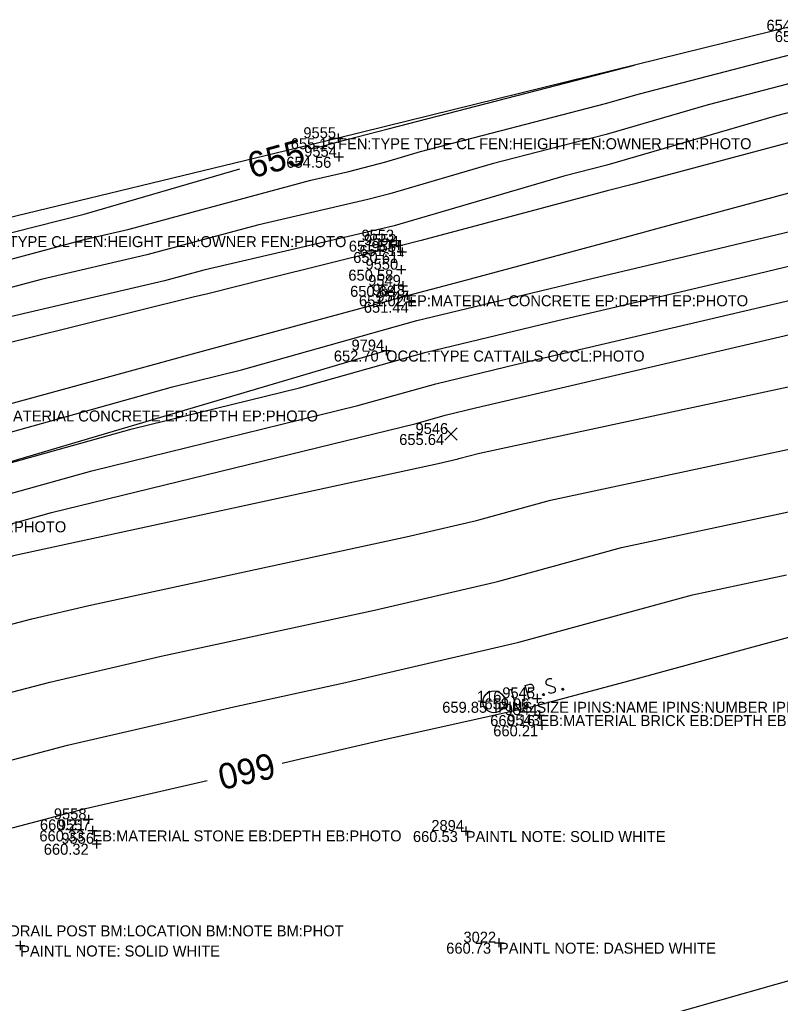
# Model space of a CAD drawing. Extents: x 2129350 to 2137777, y 657588 to 659885.
# Drawn here: x 2134268.7 to 2134351.9, y 659078.5 to 659186 of the extents above; entities that cross this region are included whole.
import ezdxf

# ---------------------------------------------------------------- set-up
doc = ezdxf.new("R2010")
doc.units = 0
for name, color, linetype in [('DT_X_Contour_Major', 7, 'Continuous'), ('DT_X_Contour_Minor', 7, 'Continuous'), ('DT_X_TIN_Hull', 7, 'Continuous'), ('PV_X_COP', 7, 'Continuous'), ('SV_P_Mon_Cells_Set', 7, 'Continuous'), ('SV_X_Occupation_Line', 7, 'Continuous'), ('SV_X_Random_Point', 7, 'Continuous'), ('SV_X_Shot_Marker', 7, 'Continuous'), ('SV_X_Text_Comment', 7, 'Continuous'), ('SV_X_Text_Elevation', 7, 'Continuous'), ('SV_X_Text_Name', 7, 'Continuous')]:
    doc.layers.add(name, color=color, linetype=linetype)

msp = doc.modelspace()

# ---------------------------------------------------------------- linework, layer by layer
at = {"layer": 'DT_X_Contour_Major'}
for points in [[(2134300.87, 659171.9), (2134303.53, 659172.62), (2134304.47, 659172.86), (2134309.01, 659174.04), (2134335.93, 659181)], [(2134195.69, 659145.79), (2134216.4, 659150.64), (2134219.64, 659151.42), (2134235.81, 659155.2), (2134255.8, 659159.88), (2134260.05, 659160.76), (2134275.77, 659164.7), (2134292.78, 659169.65)], [(2134259.01, 659128.73), (2134262.9, 659129.67), (2134267.26, 659130.72), (2134272.2, 659132.1), (2134312.05, 659141.85), (2134315.24, 659142.75), (2134318.55, 659143.54), (2134356.18, 659152.33)], [(2134297.41, 659104.74), (2134300.03, 659105.35), (2134300.54, 659105.46), (2134308.9, 659107.4), (2134317.93, 659109.37), (2134324.93, 659110.95), (2134325.38, 659111.05), (2134335.3, 659113.73), (2134348.51, 659117.34), (2134360.34, 659120.53), (2134371.28, 659123.52), (2134393.63, 659129.35), (2134394.27, 659129.51)], [(2134192.04, 659079.6), (2134201.65, 659081.72), (2134201.85, 659081.78), (2134201.93, 659081.92), (2134203.56, 659082.44), (2134216.42, 659084.98), (2134222.44, 659086.3), (2134228.12, 659087.64), (2134230.5, 659088.18), (2134236.1, 659089.42), (2134246.48, 659092.02), (2134254.29, 659094.11), (2134254.9, 659094.24), (2134275.91, 659099.77), (2134289.22, 659102.85)]]:
    msp.add_lwpolyline(points, dxfattribs=at)
at = {"layer": 'DT_X_Contour_Minor'}
for points in [[(2134152.76, 659131.84), (2134168.03, 659135.54), (2134168.24, 659135.6), (2134176.5, 659137.84), (2134192.24, 659141.51), (2134200.65, 659143.79), (2134216.49, 659147.5), (2134224.81, 659149.5), (2134236.7, 659152.28), (2134254.85, 659156.52), (2134260.96, 659157.99), (2134275.77, 659161.94), (2134280.7, 659163.09), (2134300.56, 659168.43), (2134304.69, 659169.39), (2134308.74, 659170.44), (2134312.54, 659171.55), (2134332.75, 659176.79), (2134336.49, 659177.87), (2134356.95, 659183.17)], [(2134357, 659180.03), (2134343.97, 659176.66), (2134332.83, 659173.43), (2134320.38, 659170.2), (2134309.2, 659166.94), (2134306.79, 659166.32), (2134294.71, 659163.52), (2134282.62, 659160.26), (2134271.08, 659157.58), (2134261.88, 659155.12), (2134249.21, 659152.07), (2134237.6, 659149.36), (2134229.99, 659147.58), (2134216.57, 659144.35), (2134206.19, 659141.92), (2134192.34, 659138.17), (2134182.17, 659135.8), (2134168.28, 659132.03), (2134167.92, 659131.93), (2134158.21, 659129.58)], [(2134357.06, 659176.9), (2134351.46, 659175.45), (2134332.91, 659170.07), (2134328.21, 659168.85), (2134309.66, 659163.45), (2134308.89, 659163.25), (2134288.86, 659158.6), (2134284.53, 659157.44), (2134266.4, 659153.21), (2134262.8, 659152.25), (2134243.57, 659147.62), (2134238.49, 659146.44), (2134235.17, 659145.66), (2134216.66, 659141.21), (2134211.73, 659140.06), (2134192.45, 659134.84), (2134187.85, 659133.76), (2134168.32, 659128.46), (2134167.81, 659128.32), (2134163.65, 659127.32), (2134143.51, 659122.48)], [(2134354.27, 659172.9), (2134335.82, 659167.99), (2134332.96, 659167.27), (2134312.59, 659161.84), (2134310.18, 659161.23), (2134308.22, 659160.74), (2134295.76, 659157.65), (2134289.27, 659156.02), (2134287.68, 659155.64), (2134269.19, 659151.04), (2134263.57, 659149.7), (2134247.74, 659145.92), (2134240.17, 659144.03), (2134226.21, 659140.7), (2134216.67, 659138.28), (2134216.49, 659138.23), (2134204.56, 659135.1), (2134192.21, 659131.83), (2134182.68, 659129.32), (2134167.97, 659125.44), (2134167.73, 659125.38), (2134163.65, 659124.36), (2134152.8, 659121.69)], [(2134149.54, 659114.15), (2134168.53, 659118.99), (2134169.51, 659119.25), (2134176.36, 659121.06), (2134193.45, 659125.56), (2134215.07, 659131.32), (2134217.44, 659131.95), (2134217.78, 659132.04), (2134219.45, 659132.44), (2134241.19, 659137.52), (2134253.61, 659140.56), (2134264.15, 659143.06), (2134281.64, 659147.81), (2134287.19, 659149.33), (2134309.81, 659155.46), (2134311.1, 659155.81), (2134317.07, 659157.39), (2134335.2, 659162.28), (2134338.65, 659163.23), (2134359.31, 659168.81)], [(2134143.24, 659109.7), (2134164.52, 659115.16), (2134169.55, 659116.45), (2134190.08, 659121.55), (2134209.48, 659126.37), (2134227.5, 659131.1), (2134227.81, 659131.17), (2134246.92, 659135.78), (2134264.95, 659140.12), (2134285.42, 659145.84), (2134292.96, 659147.69), (2134312.13, 659153.08), (2134332.05, 659157.88), (2134341.43, 659160.07), (2134360.86, 659164.73)], [(2134149.49, 659107.65), (2134166.17, 659111.93), (2134170.12, 659112.94), (2134186.21, 659116.94), (2134201.41, 659120.72), (2134237.74, 659130.24), (2134237.97, 659130.3), (2134252.24, 659133.74), (2134265.72, 659136.99), (2134281.01, 659141.26), (2134299.32, 659145.74), (2134313.17, 659149.64), (2134327.55, 659153.1), (2134348.69, 659158.03), (2134362.22, 659161.28)], [(2134155.75, 659105.6), (2134167.83, 659108.7), (2134170.68, 659109.44), (2134182.33, 659112.33), (2134193.34, 659115.07), (2134247.98, 659129.39), (2134248.13, 659129.43), (2134257.57, 659131.71), (2134266.49, 659133.85), (2134276.6, 659136.68), (2134305.69, 659143.8), (2134314.2, 659146.19), (2134323.05, 659148.32), (2134355.95, 659156)], [(2134127.59, 659090.34), (2134168.25, 659101.51), (2134171.13, 659102.25), (2134171.81, 659102.42), (2134174.59, 659103.11), (2134177.21, 659103.77), (2134261.53, 659125.87), (2134265.68, 659126.88), (2134267.84, 659127.35), (2134268.08, 659127.41), (2134268.35, 659127.48), (2134314.46, 659137.47), (2134316.66, 659137.98), (2134316.74, 659138), (2134318.98, 659138.61), (2134362.91, 659148.03)], [(2134154.98, 659094.1), (2134169.97, 659096.91), (2134172.67, 659097.63), (2134174.56, 659097.76), (2134174.91, 659097.83), (2134220.76, 659109.32), (2134222.58, 659109.9), (2134223.89, 659110.16), (2134224.07, 659110.19), (2134225.39, 659110.54), (2134264.61, 659119.07), (2134270.04, 659120.5), (2134276.27, 659121.94), (2134310.98, 659129.47), (2134318.67, 659131.25), (2134318.92, 659131.31), (2134326.75, 659133.45), (2134359.46, 659140.46)], [(2134127.31, 659081.14), (2134164.1, 659088.04), (2134174.01, 659090.7), (2134180.94, 659091.15), (2134182.24, 659091.4), (2134204.15, 659096.9), (2134216.24, 659100.74), (2134225.04, 659102.48), (2134226.23, 659102.72), (2134235.02, 659105.07), (2134261.37, 659110.8), (2134272, 659113.59), (2134284.19, 659116.41), (2134307.5, 659121.46), (2134320.67, 659124.52), (2134321.1, 659124.62), (2134334.51, 659128.28), (2134356.01, 659132.89)], [(2134158.23, 659079.17), (2134175.35, 659083.76), (2134186.81, 659084.51), (2134186.86, 659084.53), (2134187.34, 659084.2), (2134188.45, 659084.18), (2134189.48, 659084.43), (2134189.96, 659085.24), (2134209.9, 659091.59), (2134226.18, 659094.81), (2134228.38, 659095.24), (2134244.66, 659099.59), (2134258.14, 659102.52), (2134273.96, 659106.68), (2134292.11, 659110.88), (2134304.02, 659113.46), (2134322.68, 659117.79), (2134323.28, 659117.93), (2134342.28, 659123.12), (2134352.56, 659125.32)]]:
    msp.add_lwpolyline(points, dxfattribs=at)
at = {"layer": 'DT_X_TIN_Hull'}
msp.add_lwpolyline([(2134356.03, 659185.95), (2134303.52, 659173.01), (2134259.23, 659162.31), (2134216.07, 659153.31), (2134168.25, 659141.96), (2134125.88, 659132.55), (2134109.05, 659128.86), (2134056.89, 659117.03), (2133999.59, 659103.37), (2133973.21, 659091.25), (2133972.95, 659091.39), (2133971.1, 659091.46), (2133969.76, 659091.14), (2133967.6, 659091.08), (2133965.7, 659091.19), (2133965.45, 659091.23), (2133933.98, 659084.79), (2133923.28, 659083.03), (2133873.95, 659069.27), (2133819.31, 659054.81), (2133767.48, 659040.46), (2133725.98, 659030.57)], dxfattribs=at)
at = {"layer": 'PV_X_COP'}
msp.add_lwpolyline([(2134372.8, 659086.61), (2134323.79, 659072.7), (2134275.99, 659059.69), (2134222.68, 659044.63), (2134179.75, 659033.13), (2134131.31, 659020.04), (2134083.27, 659006.66), (2134034.91, 658993.22), (2133987.27, 658980.27), (2133938.9, 658966.72), (2133890.03, 658953.66), (2133841.98, 658940.1), (2133794.81, 658927.21), (2133746.12, 658913.94)], dxfattribs=at)
at = {"layer": 'SV_P_Mon_Cells_Set'}
for points in [[(2134324.41, 659111.67), (2134323.98, 659113.21), (2134324.49, 659113.35), (2134324.55, 659113.35), (2134324.63, 659113.35), (2134324.67, 659113.33), (2134324.7, 659113.32), (2134324.76, 659113.27), (2134324.81, 659113.22), (2134324.86, 659113.13), (2134324.9, 659112.98), (2134324.9, 659112.93), (2134324.9, 659112.85), (2134324.88, 659112.75), (2134324.85, 659112.71), (2134324.83, 659112.67), (2134324.78, 659112.63), (2134324.7, 659112.6), (2134324.19, 659112.46)], [(2134326.91, 659113.9), (2134326.88, 659113.92), (2134326.84, 659113.94), (2134326.74, 659113.95), (2134326.61, 659113.94), (2134326.53, 659113.92), (2134326.5, 659113.91), (2134326.37, 659113.83), (2134326.27, 659113.73), (2134326.22, 659113.61), (2134326.23, 659113.51), (2134326.25, 659113.43), (2134326.3, 659113.34), (2134326.41, 659113.28), (2134327.09, 659113.08), (2134327.16, 659113.05), (2134327.19, 659113), (2134327.23, 659112.94), (2134327.25, 659112.86), (2134327.26, 659112.79), (2134327.27, 659112.74), (2134327.26, 659112.67), (2134327.26, 659112.61), (2134327.24, 659112.57), (2134327.22, 659112.53), (2134327.2, 659112.49), (2134327.16, 659112.46), (2134327.13, 659112.44), (2134327.04, 659112.4), (2134326.89, 659112.36), (2134326.79, 659112.35), (2134326.63, 659112.4), (2134326.52, 659112.45)], [(2134328.04, 659112.9), (2134328.09, 659112.91), (2134328.13, 659112.9), (2134328.17, 659112.86), (2134328.19, 659112.79), (2134328.17, 659112.74), (2134328.15, 659112.7), (2134328.09, 659112.69), (2134328.05, 659112.71), (2134328.01, 659112.74), (2134327.99, 659112.81), (2134328.01, 659112.86), (2134328.04, 659112.9)], [(2134322.3, 659112.74), (2134322.64, 659112.84)], [(2134322.9, 659111.25), (2134322.47, 659112.79)], [(2134325.93, 659112.31), (2134325.98, 659112.33), (2134326.02, 659112.31), (2134326.07, 659112.27), (2134326.09, 659112.21), (2134326.07, 659112.15), (2134326.04, 659112.12), (2134325.99, 659112.11), (2134325.95, 659112.12), (2134325.91, 659112.16), (2134325.89, 659112.22), (2134325.91, 659112.28), (2134325.93, 659112.31)], [(2134322.73, 659111.2), (2134323.07, 659111.3)], [(2134323.76, 659111.71), (2134323.82, 659111.73), (2134323.86, 659111.71), (2134323.9, 659111.67), (2134323.92, 659111.61), (2134323.9, 659111.55), (2134323.88, 659111.52), (2134323.82, 659111.51), (2134323.78, 659111.52), (2134323.74, 659111.56), (2134323.72, 659111.62), (2134323.74, 659111.68), (2134323.76, 659111.71)]]:
    msp.add_lwpolyline(points, dxfattribs=at)
msp.add_circle((2134320.57, 659111.43), 1.2, dxfattribs=at)
at = {"layer": 'SV_X_Occupation_Line'}
msp.add_lwpolyline([(2133964.23, 659050.82), (2133988.96, 659052.85), (2134023.9, 659066.14), (2134068.85, 659084.35), (2134158.11, 659108.79), (2134245.54, 659131.15), (2134308.77, 659149.81)], dxfattribs=at)
at = {"layer": 'SV_X_Random_Point'}
for p, q in [((2134315.19, 659140.02), (2134316.53, 659141.36)), ((2134315.19, 659141.36), (2134316.53, 659140.02))]:
    msp.add_line(p, q, dxfattribs=at)
at = {"layer": 'SV_X_Shot_Marker'}
for p, q in [((2134303.52, 659173.51), (2134303.52, 659172.51)), ((2134303.02, 659173.01), (2134304.02, 659173.01)), ((2134303.52, 659173.01), (2134303.52, 659173.01)), ((2134303.1, 659170.98), (2134304.1, 659170.98)), ((2134303.6, 659171.48), (2134303.6, 659170.48)), ((2134303.6, 659170.98), (2134303.6, 659170.98)), ((2134309.37, 659161.82), (2134310.37, 659161.82)), ((2134309.62, 659161.33), (2134310.62, 659161.33)), ((2134309.87, 659162.32), (2134309.87, 659161.32)), ((2134309.87, 659161.82), (2134309.87, 659161.82)), ((2134310.12, 659161.83), (2134310.12, 659160.83)), ((2134310.12, 659161.33), (2134310.12, 659161.33)), ((2134310.02, 659160.58), (2134311.02, 659160.58)), ((2134310.52, 659161.08), (2134310.52, 659160.08)), ((2134310.52, 659160.58), (2134310.52, 659160.58)), ((2134310.42, 659159.15), (2134310.42, 659158.15)), ((2134309.92, 659158.65), (2134310.92, 659158.65)), ((2134310.42, 659158.65), (2134310.42, 659158.65)), ((2134310.62, 659157.38), (2134310.62, 659156.38)), ((2134310.12, 659156.88), (2134311.12, 659156.88)), ((2134310.62, 659156.88), (2134310.62, 659156.88)), ((2134311.08, 659156.34), (2134311.08, 659155.34)), ((2134310.58, 659155.84), (2134311.58, 659155.84)), ((2134311.01, 659155.14), (2134312.01, 659155.14)), ((2134311.08, 659155.84), (2134311.08, 659155.84)), ((2134311.51, 659155.64), (2134311.51, 659154.64)), ((2134311.51, 659155.14), (2134311.51, 659155.14)), ((2134308.27, 659149.81), (2134309.27, 659149.81)), ((2134308.77, 659150.31), (2134308.77, 659149.31)), ((2134308.77, 659149.81), (2134308.77, 659149.81)), ((2134324.78, 659111.81), (2134325.78, 659111.81)), ((2134325.28, 659112.31), (2134325.28, 659111.31)), ((2134325.28, 659111.81), (2134325.28, 659111.81)), ((2134325.04, 659109.98), (2134326.04, 659109.98)), ((2134325.54, 659110.48), (2134325.54, 659109.48)), ((2134325.54, 659109.98), (2134325.54, 659109.98)), ((2134325.31, 659108.86), (2134326.31, 659108.86)), ((2134325.81, 659109.36), (2134325.81, 659108.36)), ((2134325.81, 659108.86), (2134325.81, 659108.86)), ((2134276.25, 659099.09), (2134276.25, 659098.09)), ((2134275.75, 659098.59), (2134276.75, 659098.59)), ((2134276.25, 659098.59), (2134276.25, 659098.59)), ((2134276.67, 659097.88), (2134276.67, 659096.88)), ((2134276.17, 659097.38), (2134277.17, 659097.38)), ((2134276.67, 659097.38), (2134276.67, 659097.38)), ((2134316.98, 659097.31), (2134317.98, 659097.31)), ((2134317.48, 659097.81), (2134317.48, 659096.81)), ((2134317.48, 659097.31), (2134317.48, 659097.31)), ((2134276.63, 659095.92), (2134277.63, 659095.92)), ((2134277.13, 659096.42), (2134277.13, 659095.42)), ((2134277.13, 659095.92), (2134277.13, 659095.92)), ((2134268.77, 659085.3), (2134268.77, 659084.3)), ((2134320.61, 659085.11), (2134321.61, 659085.11)), ((2134321.11, 659085.61), (2134321.11, 659084.61)), ((2134321.11, 659085.11), (2134321.11, 659085.11)), ((2134268.27, 659084.8), (2134269.27, 659084.8)), ((2134268.77, 659084.8), (2134268.77, 659084.8))]:
    msp.add_line(p, q, dxfattribs=at)

# ---------------------------------------------------------------- texts
at = {"layer": 'DT_X_Contour_Major'}
for s, rotation, p in [('655', 15.5327, (2134294.1, 659168.6)), ('660', 193.0186, (2134296.26, 659105.91))]:
    msp.add_text(s, height=2.8, rotation=rotation, dxfattribs=at).set_placement(p)
at = {"layer": 'SV_X_Text_Comment'}
for s, p in [('FEN:TYPE TYPE CL FEN:HEIGHT FEN:OWNER FEN:PHOTO', (2134303.52, 659171.81)), ('FEN:TYPE TYPE CL FEN:HEIGHT FEN:OWNER FEN:PHOTO', (2134259.23, 659161.11)), ('EP:MATERIAL CONCRETE EP:DEPTH EP:PHOTO', (2134311.08, 659154.65)), ('OCCL:TYPE CATTAILS OCCL:PHOTO', (2134308.77, 659148.61)), ('EP:MATERIAL CONCRETE EP:DEPTH EP:PHOTO', (2134264.06, 659142.06)), ('OCCL:TYPE CATTAILS OCCL:PHOTO', (2134245.54, 659129.95)), ('IPINS:SIZE IPINS:NAME IPINS:NUMBER IPINS:NOTE IPINS:PHOTO', (2134320.57, 659110.23)), ('EB:MATERIAL BRICK EB:DEPTH EB:PHOTO', (2134325.54, 659108.78)), ('EB:MATERIAL STONE EB:DEPTH EB:PHOTO', (2134276.67, 659096.18)), ('PAINTL NOTE: SOLID WHITE', (2134317.48, 659096.11)), ('BM:DESCRIPTION BENCH TIE EASTERN GUARDRAIL POST BM:LOCATION BM:NOTE BM:PHOT', (2134231.64, 659085.8)), ('PAINTL NOTE: DASHED WHITE', (2134321.11, 659083.91)), ('PAINTL NOTE: SOLID WHITE', (2134268.77, 659083.6))]:
    msp.add_text(s, height=1.2, dxfattribs=at).set_placement(p)
at = {"layer": 'SV_X_Text_Elevation'}
for s, p in [('654.97', (2134350.36, 659184.75)), ('654.53', (2134351.27, 659183.52)), ('655.15', (2134298.35, 659171.81)), ('654.56', (2134297.87, 659169.78)), ('651.57', (2134304.7, 659160.62)), ('651.11', (2134305.86, 659160.13)), ('650.61', (2134305.18, 659159.38)), ('650.58', (2134304.65, 659157.45)), ('650.68', (2134304.84, 659155.68)), ('651.02', (2134305.81, 659154.65)), ('651.44', (2134306.34, 659153.94)), ('652.70', (2134303.06, 659148.61)), ('655.64', (2134310.21, 659139.49)), ('659.96', (2134319.53, 659110.61)), ('659.85', (2134314.91, 659110.23)), ('660.16', (2134320.16, 659108.78)), ('660.21', (2134320.49, 659107.66)), ('660.21', (2134270.93, 659097.39)), ('660.33', (2134270.87, 659096.18)), ('660.53', (2134311.71, 659096.11)), ('660.32', (2134271.35, 659094.72)), ('660.73', (2134315.35, 659083.91))]:
    msp.add_text(s, height=1.2, dxfattribs=at).set_placement(p)
at = {"layer": 'SV_X_Text_Name'}
for s, p in [('9555', (2134299.73, 659173.01)), ('9554', (2134299.82, 659170.98)), ('9553', (2134306.08, 659161.82)), ('9552', (2134306.35, 659161.33)), ('9551', (2134307.17, 659160.58)), ('9550', (2134306.52, 659158.65)), ('9549', (2134306.81, 659156.88)), ('9548', (2134307.28, 659155.84)), ('9547', (2134307.71, 659155.14)), ('9794', (2134304.99, 659149.81)), ('9546', (2134311.99, 659140.69)), ('9545', (2134321.48, 659111.81)), ('116', (2134318.71, 659111.43)), ('9544', (2134321.75, 659109.98)), ('9543', (2134322.02, 659108.86)), ('9558', (2134272.45, 659098.59)), ('9557', (2134272.88, 659097.38)), ('2894', (2134313.72, 659097.31)), ('9556', (2134273.27, 659095.92)), ('3022', (2134317.23, 659085.11))]:
    msp.add_text(s, height=1.2, dxfattribs=at).set_placement(p)

doc.saveas('drawing.dxf')
